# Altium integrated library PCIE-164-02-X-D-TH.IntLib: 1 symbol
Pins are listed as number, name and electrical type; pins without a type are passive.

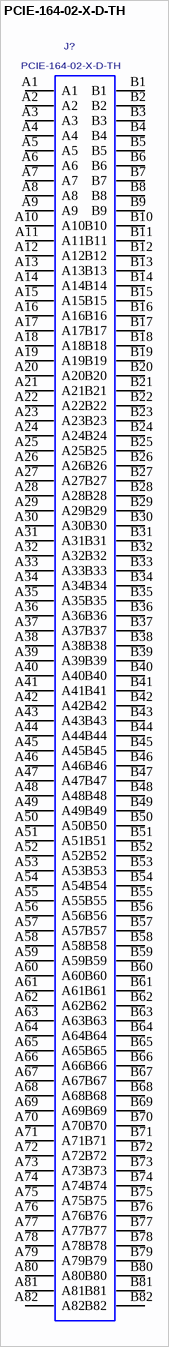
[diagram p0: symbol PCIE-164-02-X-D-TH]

## PCIE-164-02-X-D-TH
designator J?
PCI EXPRESS CARD CONNECTOR ,164 PINS.; MANUFACTURER: SAMTEC
footprint PCIE-164-02-X-D-TH
pins: A1, A2, A3, A4, A5, A6, A7, A8, A9, A10, A11, A12, A13, A14, A15, A16, A17, A18, A19, A20, A21, A22, A23, A24, A25, A26, A27, A28, A29, A30, A31, A32, A33, A34, A35, A36, A37, A38, A39, A40, A41, A42, A43, A44, A45, A46, A47, A48, A49, A50, A51, A52, A53, A54, A55, A56, A57, A58, A59, A60, A61, A62, A63, A64, A65, A66, A67, A68, A69, A70, A71, A72, A73, A74, A75, A76, A77, A78, A79, A80, A81, A82, B1, B2, B3, B4, B5, B6, B7, B8, B9, B10, B11, B12, B13, B14, B15, B16, B17, B18, B19, B20, B21, B22, B23, B24, B25, B26, B27, B28, B29, B30, B31, B32, B33, B34, B35, B36, B37, B38, B39, B40, B41, B42, B43, B44, B45, B46, B47, B48, B49, B50, B51, B52, B53, B54, B55, B56, B57, B58, B59, B60, B61, B62, B63, B64, B65, B66, B67, B68, B69, B70, B71, B72, B73, B74, B75, B76, B77, B78, B79, B80, B81, B82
